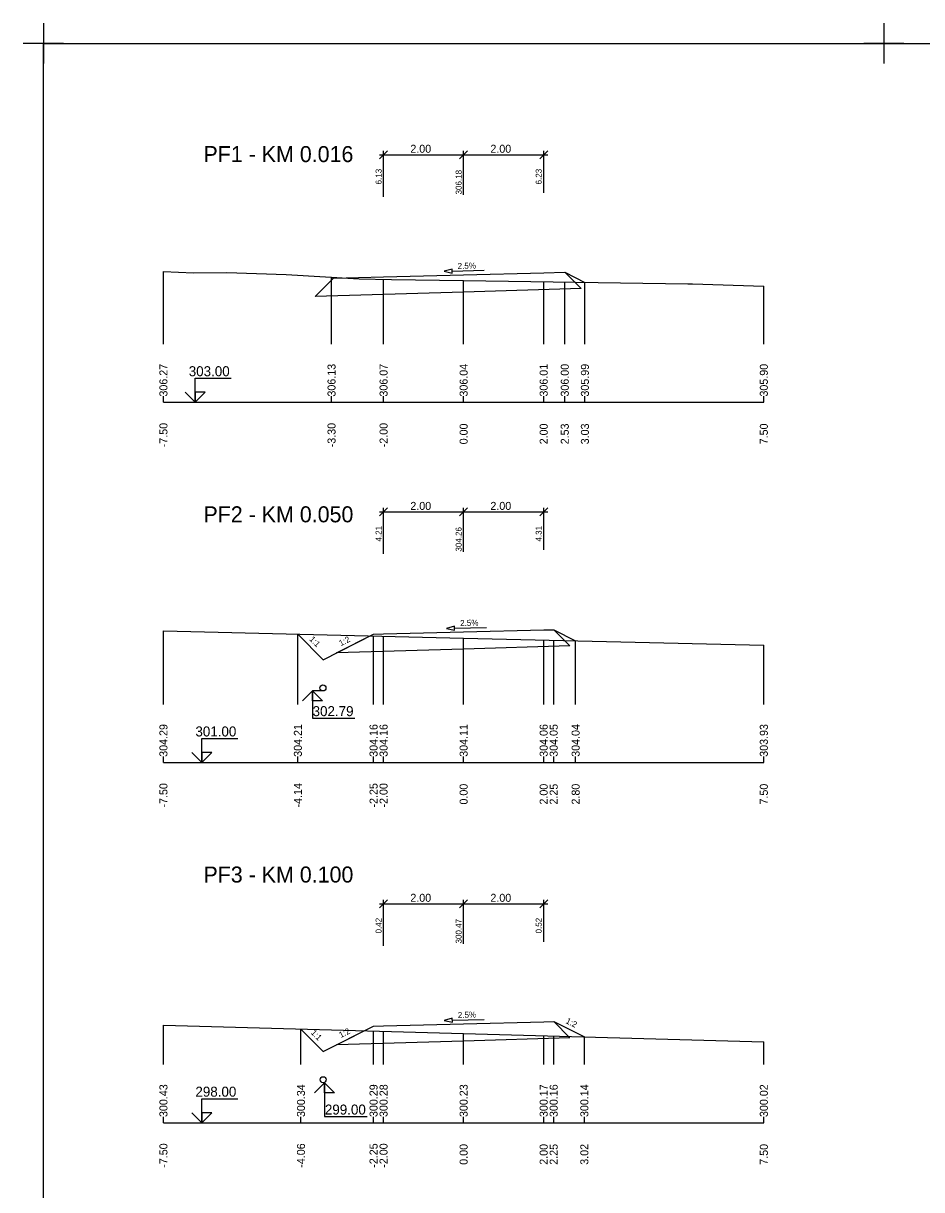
# Model space of a CAD drawing. Extents: x -5 to 1895, y -2 to 602.
# Drawn here: x -5 to 219.4, y 310.3 to 601.7 of the extents above; entities that cross this region are included whole.
import ezdxf

# ---------------------------------------------------------------- set-up
doc = ezdxf.new("R2010")
doc.units = 0
for name, color, linetype in [('KOTA', 7, 'Continuous'), ('KOTA_DELKY', 7, 'Continuous'), ('KOTA_DELKY_CONT', 7, 'Continuous'), ('KRIZENI', 7, 'Continuous'), ('NS_TELESO_VOZOVKY', 7, 'Continuous'), ('NS_V_PF', 7, 'Continuous'), ('REZY_PF_PUVODNI', 7, 'Continuous'), ('SESTAVY_REZU_PF', 7, 'Continuous'), ('SKLON', 7, 'Continuous'), ('SVK', 7, 'Continuous')]:
    doc.layers.add(name, color=color, linetype=linetype)

msp = doc.modelspace()

# ---------------------------------------------------------------- linework, layer by layer
for p, q in [((0, 601.67), (0, 591.67)), ((0, 601.67), (0, 591.67)), ((0, 601.67), (0, 591.67)), ((0, 601.67), (0, 591.67)), ((0, 601.67), (0, 591.67)), ((0, 601.67), (0, 591.67)), ((0, 601.67), (0, 591.67)), ((0, 601.67), (0, 591.67)), ((0, 601.67), (0, 591.67)), ((0, 601.67), (0, 591.67)), ((0, 601.67), (0, 591.67)), ((0, 601.67), (0, 591.67)), ((0, 601.67), (0, 591.67)), ((0, 601.67), (0, 591.67)), ((0, 601.67), (0, 591.67)), ((0, 601.67), (0, 591.67)), ((0, 601.67), (0, 591.67)), ((0, 601.67), (0, 591.67)), ((0, 601.67), (0, 591.67)), ((0, 601.67), (0, 591.67)), ((0, 601.67), (0, 591.67)), ((0, 601.67), (0, 591.67)), ((0, 601.67), (0, 591.67)), ((0, 601.67), (0, 591.67)), ((0, 601.67), (0, 591.67)), ((0, 601.67), (0, 591.67)), ((0, 601.67), (0, 591.67)), ((0, 601.67), (0, 591.67)), ((0, 601.67), (0, 591.67)), ((0, 601.67), (0, 591.67)), ((0, 601.67), (0, 591.67)), ((0, 601.67), (0, 591.67)), ((0, 601.67), (0, 591.67)), ((0, 601.67), (0, 591.67)), ((0, 601.67), (0, 591.67)), ((0, 601.67), (0, 591.67)), ((210, 601.67), (210, 591.67)), ((210, 601.67), (210, 591.67)), ((210, 601.67), (210, 591.67)), ((210, 601.67), (210, 591.67)), ((210, 601.67), (210, 591.67)), ((210, 601.67), (210, 591.67)), ((210, 601.67), (210, 591.67)), ((210, 601.67), (210, 591.67)), ((210, 601.67), (210, 591.67)), ((210, 601.67), (210, 591.67)), ((210, 601.67), (210, 591.67)), ((210, 601.67), (210, 591.67)), ((210, 601.67), (210, 591.67)), ((210, 601.67), (210, 591.67)), ((210, 601.67), (210, 591.67)), ((210, 601.67), (210, 591.67)), ((210, 601.67), (210, 591.67)), ((210, 601.67), (210, 591.67)), ((210, 601.67), (210, 591.67)), ((210, 601.67), (210, 591.67)), ((210, 601.67), (210, 591.67)), ((210, 601.67), (210, 591.67)), ((210, 601.67), (210, 591.67)), ((210, 601.67), (210, 591.67)), ((210, 601.67), (210, 591.67)), ((210, 601.67), (210, 591.67)), ((210, 601.67), (210, 591.67)), ((210, 601.67), (210, 591.67)), ((210, 601.67), (210, 591.67)), ((210, 601.67), (210, 591.67)), ((210, 601.67), (210, 591.67)), ((210, 601.67), (210, 591.67)), ((210, 601.67), (210, 591.67)), ((210, 601.67), (210, 591.67)), ((210, 601.67), (210, 591.67)), ((210, 601.67), (210, 591.67)), ((210, 601.67), (210, 591.67)), ((210, 601.67), (210, 591.67)), ((210, 601.67), (210, 591.67)), ((210, 601.67), (210, 591.67)), ((210, 601.67), (210, 591.67)), ((210, 601.67), (210, 591.67)), ((210, 601.67), (210, 591.67)), ((210, 601.67), (210, 591.67)), ((210, 601.67), (210, 591.67)), ((210, 601.67), (210, 591.67)), ((210, 601.67), (210, 591.67)), ((210, 601.67), (210, 591.67)), ((210, 601.67), (210, 591.67)), ((210, 601.67), (210, 591.67)), ((210, 601.67), (210, 591.67)), ((210, 601.67), (210, 591.67)), ((210, 601.67), (210, 591.67)), ((210, 601.67), (210, 591.67)), ((5, 596.67), (-5, 596.67)), ((5, 596.67), (-5, 596.67)), ((5, 596.67), (-5, 596.67)), ((5, 596.67), (-5, 596.67)), ((5, 596.67), (-5, 596.67)), ((5, 596.67), (-5, 596.67)), ((5, 596.67), (-5, 596.67)), ((5, 596.67), (-5, 596.67)), ((5, 596.67), (-5, 596.67)), ((5, 596.67), (-5, 596.67)), ((5, 596.67), (-5, 596.67)), ((5, 596.67), (-5, 596.67)), ((5, 596.67), (-5, 596.67)), ((5, 596.67), (-5, 596.67)), ((5, 596.67), (-5, 596.67)), ((5, 596.67), (-5, 596.67)), ((5, 596.67), (-5, 596.67)), ((5, 596.67), (-5, 596.67)), ((5, 596.67), (-5, 596.67)), ((5, 596.67), (-5, 596.67)), ((5, 596.67), (-5, 596.67)), ((5, 596.67), (-5, 596.67)), ((5, 596.67), (-5, 596.67)), ((5, 596.67), (-5, 596.67)), ((5, 596.67), (-5, 596.67)), ((5, 596.67), (-5, 596.67)), ((5, 596.67), (-5, 596.67)), ((5, 596.67), (-5, 596.67)), ((5, 596.67), (-5, 596.67)), ((5, 596.67), (-5, 596.67)), ((5, 596.67), (-5, 596.67)), ((5, 596.67), (-5, 596.67)), ((5, 596.67), (-5, 596.67)), ((5, 596.67), (-5, 596.67)), ((5, 596.67), (-5, 596.67)), ((5, 596.67), (-5, 596.67)), ((215, 596.67), (205, 596.67)), ((215, 596.67), (205, 596.67)), ((215, 596.67), (205, 596.67)), ((215, 596.67), (205, 596.67)), ((215, 596.67), (205, 596.67)), ((215, 596.67), (205, 596.67)), ((215, 596.67), (205, 596.67)), ((215, 596.67), (205, 596.67)), ((215, 596.67), (205, 596.67)), ((215, 596.67), (205, 596.67)), ((215, 596.67), (205, 596.67)), ((215, 596.67), (205, 596.67)), ((215, 596.67), (205, 596.67)), ((215, 596.67), (205, 596.67)), ((215, 596.67), (205, 596.67)), ((215, 596.67), (205, 596.67)), ((215, 596.67), (205, 596.67)), ((215, 596.67), (205, 596.67)), ((215, 596.67), (205, 596.67)), ((215, 596.67), (205, 596.67)), ((215, 596.67), (205, 596.67)), ((215, 596.67), (205, 596.67)), ((215, 596.67), (205, 596.67)), ((215, 596.67), (205, 596.67)), ((215, 596.67), (205, 596.67)), ((215, 596.67), (205, 596.67)), ((215, 596.67), (205, 596.67)), ((215, 596.67), (205, 596.67)), ((215, 596.67), (205, 596.67)), ((215, 596.67), (205, 596.67)), ((215, 596.67), (205, 596.67)), ((215, 596.67), (205, 596.67)), ((215, 596.67), (205, 596.67)), ((215, 596.67), (205, 596.67)), ((215, 596.67), (205, 596.67)), ((215, 596.67), (205, 596.67)), ((215, 596.67), (205, 596.67)), ((215, 596.67), (205, 596.67)), ((215, 596.67), (205, 596.67)), ((215, 596.67), (205, 596.67)), ((215, 596.67), (205, 596.67)), ((215, 596.67), (205, 596.67)), ((215, 596.67), (205, 596.67)), ((215, 596.67), (205, 596.67)), ((215, 596.67), (205, 596.67)), ((215, 596.67), (205, 596.67)), ((215, 596.67), (205, 596.67)), ((215, 596.67), (205, 596.67)), ((215, 596.67), (205, 596.67)), ((215, 596.67), (205, 596.67)), ((215, 596.67), (205, 596.67)), ((215, 596.67), (205, 596.67)), ((215, 596.67), (205, 596.67)), ((215, 596.67), (205, 596.67))]:
    msp.add_line(p, q)
msp.add_lwpolyline([(0, 596.67), (1890, 596.67), (1890, 2.67), (0, 2.67)], close=True)
at = {"layer": 'KOTA'}
for points in [[(37.91, 507), (35.41, 509.5), (37.91, 507), (37.91, 513), (46.91, 513)], [(37.91, 507), (40.41, 509.5), (37.91, 509.5), (37.91, 507)], [(37.91, 507), (40.41, 509.5), (37.91, 509.5)], [(67.25, 434.86), (64.75, 432.36), (67.25, 434.86), (67.25, 428.04), (77.79, 428.04)], [(69.85, 434.86), (67.25, 434.86)], [(67.25, 434.86), (69.75, 432.36), (67.25, 432.36), (67.25, 434.86)], [(67.25, 434.86), (69.75, 432.36), (67.25, 432.36)], [(39.57, 417), (37.07, 419.5), (39.57, 417), (39.57, 423), (48.57, 423)], [(39.57, 417), (42.07, 419.5), (39.57, 419.5), (39.57, 417)], [(39.57, 417), (42.07, 419.5), (39.57, 419.5)], [(70.25, 336.98), (67.75, 334.48), (70.25, 336.98), (70.25, 328.53), (80.93, 328.53)], [(69.91, 336.98), (70.25, 336.98)], [(70.25, 336.98), (72.75, 334.48), (70.25, 334.48), (70.25, 336.98)], [(70.25, 336.98), (72.75, 334.48), (70.25, 334.48)], [(39.57, 327), (37.07, 329.5), (39.57, 327), (39.57, 333), (48.57, 333)], [(39.57, 327), (42.07, 329.5), (39.57, 329.5), (39.57, 327)], [(39.57, 327), (42.07, 329.5), (39.57, 329.5)]]:
    msp.add_lwpolyline(points, dxfattribs=at)
at = {"layer": 'KOTA_DELKY'}
for points in [[(84, 567.83), (86, 569.83)], [(84, 568.83), (106, 568.83)], [(85, 558.33), (85, 569.83)], [(104, 567.83), (106, 569.83)], [(104, 567.83), (106, 569.83)], [(104, 568.83), (126, 568.83)], [(105, 558.83), (105, 569.83)], [(105, 558.83), (105, 569.83)], [(124, 567.83), (126, 569.83)], [(125, 559.33), (125, 569.83)], [(84, 478.6), (86, 480.6)], [(84, 479.6), (106, 479.6)], [(85, 469.1), (85, 480.6)], [(104, 478.6), (106, 480.6)], [(104, 478.6), (106, 480.6)], [(104, 479.6), (126, 479.6)], [(105, 469.6), (105, 480.6)], [(105, 469.6), (105, 480.6)], [(124, 478.6), (126, 480.6)], [(125, 470.1), (125, 480.6)], [(84, 380.69), (86, 382.69)], [(84, 380.69), (86, 382.69)], [(85, 371.19), (85, 382.69)], [(85, 371.19), (85, 382.69)], [(104, 380.69), (106, 382.69)], [(104, 380.69), (106, 382.69)], [(104, 380.69), (106, 382.69)], [(104, 380.69), (106, 382.69)], [(105, 371.69), (105, 382.69)], [(105, 371.69), (105, 382.69)], [(105, 371.69), (105, 382.69)], [(105, 371.69), (105, 382.69)], [(124, 380.69), (126, 382.69)], [(124, 380.69), (126, 382.69)], [(125, 372.19), (125, 382.69)], [(125, 372.19), (125, 382.69)], [(84, 381.69), (106, 381.69)], [(84, 381.69), (106, 381.69)], [(104, 381.69), (126, 381.69)], [(104, 381.69), (126, 381.69)]]:
    msp.add_lwpolyline(points, dxfattribs=at)
at = {"layer": 'KRIZENI'}
for centre in [(69.85, 435.61), (69.91, 337.73)]:
    msp.add_circle(centre, 0.75, dxfattribs=at)
at = {"layer": 'NS_TELESO_VOZOVKY'}
for points in [[(105, 538.83), (125, 539.33), (130.27, 539.46), (134.33, 535.41), (105, 534.53), (67.9, 533.42), (72.5, 538.02), (85, 538.33), (105, 538.83)], [(105, 449.6), (125, 450.1), (127.5, 450.16), (131.57, 446.1), (105, 445.3), (73.2, 444.35), (82.5, 449.04), (85, 449.1), (105, 449.6)], [(105, 351.69), (125, 352.19), (127.5, 352.25), (131.57, 348.19), (105, 347.39), (73.2, 346.44), (82.5, 351.13), (85, 351.19), (105, 351.69)], [(105, 351.69), (125, 352.19), (127.5, 352.25), (131.57, 348.19), (105, 347.39), (73.2, 346.44), (82.5, 351.13), (85, 351.19), (105, 351.69)]]:
    msp.add_lwpolyline(points, dxfattribs=at)
at = {"layer": 'NS_V_PF'}
for points in [[(72, 538.27), (72.5, 538.02), (85, 538.33), (105, 538.83), (125, 539.33), (130.27, 539.46), (135.3, 536.95)], [(63.59, 449.07), (69.87, 442.66), (82.5, 449.04), (85, 449.1), (105, 449.6), (125, 450.1), (127.5, 450.16), (132.99, 447.41)], [(64.36, 350.38), (69.87, 344.76), (82.5, 351.13), (85, 351.19), (105, 351.69), (125, 352.19), (127.5, 352.25), (135.16, 348.42)], [(64.36, 350.38), (69.87, 344.76), (82.5, 351.13), (85, 351.19), (105, 351.69), (125, 352.19), (127.5, 352.25), (135.16, 348.42)]]:
    msp.add_lwpolyline(points, dxfattribs=at)
at = {"layer": 'REZY_PF_PUVODNI'}
for points in [[(30, 539.68), (37.51, 539.32), (45.81, 539.45), (60.66, 538.93), (78.9, 537.87), (87, 537.64), (105, 537.38), (161.04, 536.58), (162.2, 536.58), (180, 536.02)], [(30, 449.87), (105, 448.08), (105, 448.08), (180, 446.29)], [(30, 351.33), (105, 349.26), (105, 349.26), (180, 347.19)]]:
    msp.add_lwpolyline(points, dxfattribs=at)
at = {"layer": 'SESTAVY_REZU_PF'}
for points in [[(30, 507), (180, 507)], [(30, 417), (180, 417)], [(30, 327), (180, 327)]]:
    msp.add_lwpolyline(points, dxfattribs=at)
at = {"layer": 'SKLON'}
for points in [[(102.11, 540.26), (100.12, 539.71), (102.13, 539.26)], [(102.74, 451.04), (100.75, 450.49), (102.76, 450.04)], [(102.15, 353.12), (100.17, 352.57), (102.18, 352.12)]]:
    msp.add_lwpolyline(points, close=True, dxfattribs=at)
for points in [[(102.11, 540.26), (100.12, 539.71), (102.13, 539.26), (102.11, 540.26)], [(102.12, 539.76), (110.12, 539.96)], [(102.74, 451.04), (100.75, 450.49), (102.76, 450.04), (102.74, 451.04)], [(102.75, 450.54), (110.75, 450.74)], [(102.15, 353.12), (100.17, 352.57), (102.18, 352.12), (102.15, 353.12)], [(102.17, 352.62), (110.16, 352.82)]]:
    msp.add_lwpolyline(points, dxfattribs=at)
at = {"layer": 'SVK'}
for points in [[(30, 521.5), (30, 539.68)], [(72, 521.5), (72, 538.27)], [(85, 521.5), (85, 537.69)], [(105, 521.5), (105, 537.38)], [(125, 521.5), (125, 537.09)], [(130.27, 521.5), (130.27, 537.02)], [(135.3, 521.5), (135.3, 536.95)], [(180, 521.5), (180, 536.02)], [(30, 507), (30, 508.5)], [(72, 507), (72, 508.5)], [(85, 507), (85, 508.5)], [(105, 507), (105, 508.5)], [(125, 507), (125, 508.5)], [(130.27, 507), (130.27, 508.5)], [(135.3, 507), (135.3, 508.5)], [(180, 507), (180, 508.5)], [(30, 431.5), (30, 449.87)], [(63.59, 431.5), (63.59, 449.07)], [(82.5, 431.5), (82.5, 448.62)], [(85, 431.5), (85, 448.56)], [(105, 431.5), (105, 448.08)], [(125, 431.5), (125, 447.6)], [(127.5, 431.5), (127.5, 447.55)], [(132.99, 431.5), (132.99, 447.41)], [(180, 431.5), (180, 446.29)], [(30, 417), (30, 418.5)], [(63.59, 417), (63.59, 418.5)], [(82.5, 417), (82.5, 418.5)], [(85, 417), (85, 418.5)], [(105, 417), (105, 418.5)], [(125, 417), (125, 418.5)], [(127.5, 417), (127.5, 418.5)], [(132.99, 417), (132.99, 418.5)], [(180, 417), (180, 418.5)], [(30, 341.5), (30, 351.33)], [(64.36, 341.5), (64.36, 350.38)], [(82.5, 341.5), (82.5, 349.88)], [(85, 341.5), (85, 349.81)], [(105, 341.5), (105, 349.26)], [(125, 341.5), (125, 348.7)], [(127.5, 341.5), (127.5, 348.64)], [(135.16, 341.5), (135.16, 348.42)], [(180, 341.5), (180, 347.19)], [(30, 327), (30, 328.5)], [(64.36, 327), (64.36, 328.5)], [(82.5, 327), (82.5, 328.5)], [(85, 327), (85, 328.5)], [(105, 327), (105, 328.5)], [(125, 327), (125, 328.5)], [(127.5, 327), (127.5, 328.5)], [(135.16, 327), (135.16, 328.5)], [(180, 327), (180, 328.5)]]:
    msp.add_lwpolyline(points, dxfattribs=at)

# ---------------------------------------------------------------- texts
at = {"layer": 'KOTA'}
for s, p in [('303.00', (36.33, 513.5)), ('302.79', (67.27, 428.57)), ('301.00', (37.99, 423.5)), ('298.00', (37.99, 333.5)), ('299.00', (70.34, 329.03))]:
    msp.add_text(s, height=2.5, dxfattribs=at).set_placement(p)
at = {"layer": 'KOTA_DELKY'}
for p in [(91.69, 569.33), (111.69, 569.33), (91.69, 480.1), (111.69, 480.1), (91.69, 382.19), (91.69, 382.19), (111.69, 382.19), (111.69, 382.19)]:
    msp.add_text('2.00', height=2, dxfattribs=at).set_placement(p)
at = {"layer": 'KOTA_DELKY_CONT'}
for s, p in [('6.13', (84.5, 561.42)), ('306.18', (104.5, 558.91)), ('6.23', (124.5, 561.42)), ('4.21', (84.5, 472.19)), ('304.26', (104.5, 469.68)), ('4.31', (124.5, 472.19)), ('0.42', (84.5, 374.28)), ('0.42', (84.5, 374.28)), ('300.47', (104.5, 371.77)), ('300.47', (104.5, 371.77)), ('0.52', (124.5, 374.28)), ('0.52', (124.5, 374.28))]:
    msp.add_text(s, height=1.5, rotation=90, dxfattribs=at).set_placement(p)
at = {"layer": 'SESTAVY_REZU_PF'}
for s, p in [('PF1 - KM 0.016', (40, 567)), ('PF2 - KM 0.050', (40, 477)), ('PF3 - KM 0.100', (40, 387))]:
    msp.add_text(s, height=4, dxfattribs=at).set_placement(p)
at = {"layer": 'SKLON'}
for s, rotation, p in [('2.5%', 1.4321, (103.52, 540.29)), ('2.5%', 1.4321, (104.15, 451.08)), ('1:1', 314.4213, (66.34, 447.69)), ('1:2', 26.7649, (74.32, 446.03)), ('2.5%', 1.4321, (103.56, 353.16)), ('1:2', 333.4349, (130.37, 351.94)), ('1:1', 314.4213, (66.72, 349.39)), ('1:2', 26.7649, (74.32, 348.13)), ('1:2', 26.7649, (74.32, 348.13))]:
    msp.add_text(s, height=1.5, rotation=rotation, dxfattribs=at).set_placement(p)
at = {"layer": 'SVK'}
for s, p in [(' 306.27', (31, 507.67)), (' 306.13', (73, 507.67)), (' 306.07', (86, 507.67)), (' 306.04', (106, 507.67)), (' 306.01', (126, 507.67)), (' 306.00', (131.27, 507.67)), (' 305.99', (136.3, 507.67)), (' 305.90', (181, 507.67)), (' -7.50', (31, 495)), (' -3.30', (73, 495)), (' -2.00', (86, 495)), ('  0.00', (106, 495)), ('  2.00', (126, 495)), ('  2.53', (131.27, 495)), ('  3.03', (136.3, 495)), ('  7.50', (181, 495)), (' 304.29', (31, 417.67)), (' 304.21', (64.59, 417.67)), (' 304.16', (83.5, 417.67)), (' 304.16', (86, 417.67)), (' 304.11', (106, 417.67)), (' 304.06', (126, 417.67)), (' 304.05', (128.5, 417.67)), (' 304.04', (133.99, 417.67)), (' 303.93', (181, 417.67)), (' -7.50', (31, 405)), (' -4.14', (64.59, 405)), (' -2.25', (83.5, 405)), (' -2.00', (86, 405)), ('  0.00', (106, 405)), ('  2.00', (126, 405)), ('  2.25', (128.5, 405)), ('  2.80', (133.99, 405)), ('  7.50', (181, 405)), (' 300.43', (31, 327.67)), (' 300.34', (65.36, 327.67)), (' 300.29', (83.5, 327.67)), (' 300.28', (86, 327.67)), (' 300.23', (106, 327.67)), (' 300.17', (126, 327.67)), (' 300.16', (128.5, 327.67)), (' 300.14', (136.16, 327.67)), (' 300.02', (181, 327.67)), (' -7.50', (31, 315)), (' -4.06', (65.36, 315)), (' -2.25', (83.5, 315)), (' -2.00', (86, 315)), ('  0.00', (106, 315)), ('  2.00', (126, 315)), ('  2.25', (128.5, 315)), ('  3.02', (136.16, 315)), ('  7.50', (181, 315))]:
    msp.add_text(s, height=2, rotation=90, dxfattribs=at).set_placement(p)

doc.saveas('drawing.dxf')
